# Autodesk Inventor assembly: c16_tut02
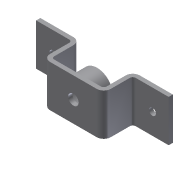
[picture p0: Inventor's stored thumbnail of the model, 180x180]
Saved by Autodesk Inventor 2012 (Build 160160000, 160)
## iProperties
Created: 2010-05
Part Number: c16_tut02
Document SubType Name: Weldment
Designer: CADSoft
Weld Material: Welded Aluminum-6061
Author: CADSoft
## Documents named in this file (3)
- C:\Users\CadCim\Documents\SAILESH\inventor-2011-fact-prt\c16-inv-2011-prt\c16_inv_2012_prt\Tutorials\c16_tut02_inv\c16_tut02.iam
- C:\Users\CadCim\Documents\SAILESH\inventor-2011-fact-prt\c16-inv-2011-prt\Tutorials\c16-tut02-inv-2011\Bracket.ipt
- C:\Users\CadCim\Documents\SAILESH\inventor-2011-fact-prt\c16-inv-2011-prt\Tutorials\c16-tut02-inv-2011\Cylinder.ipt
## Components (2 placed, 2 different names)
1. Bracket:1 — Mate:1, Mate:2
2. Cylinder:1 — Mate:1, Mate:2
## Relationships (2: Mate 2)
- Mate:1: Bracket:1 ↔ Cylinder:1
- Mate:2: Bracket:1 ↔ Cylinder:1
